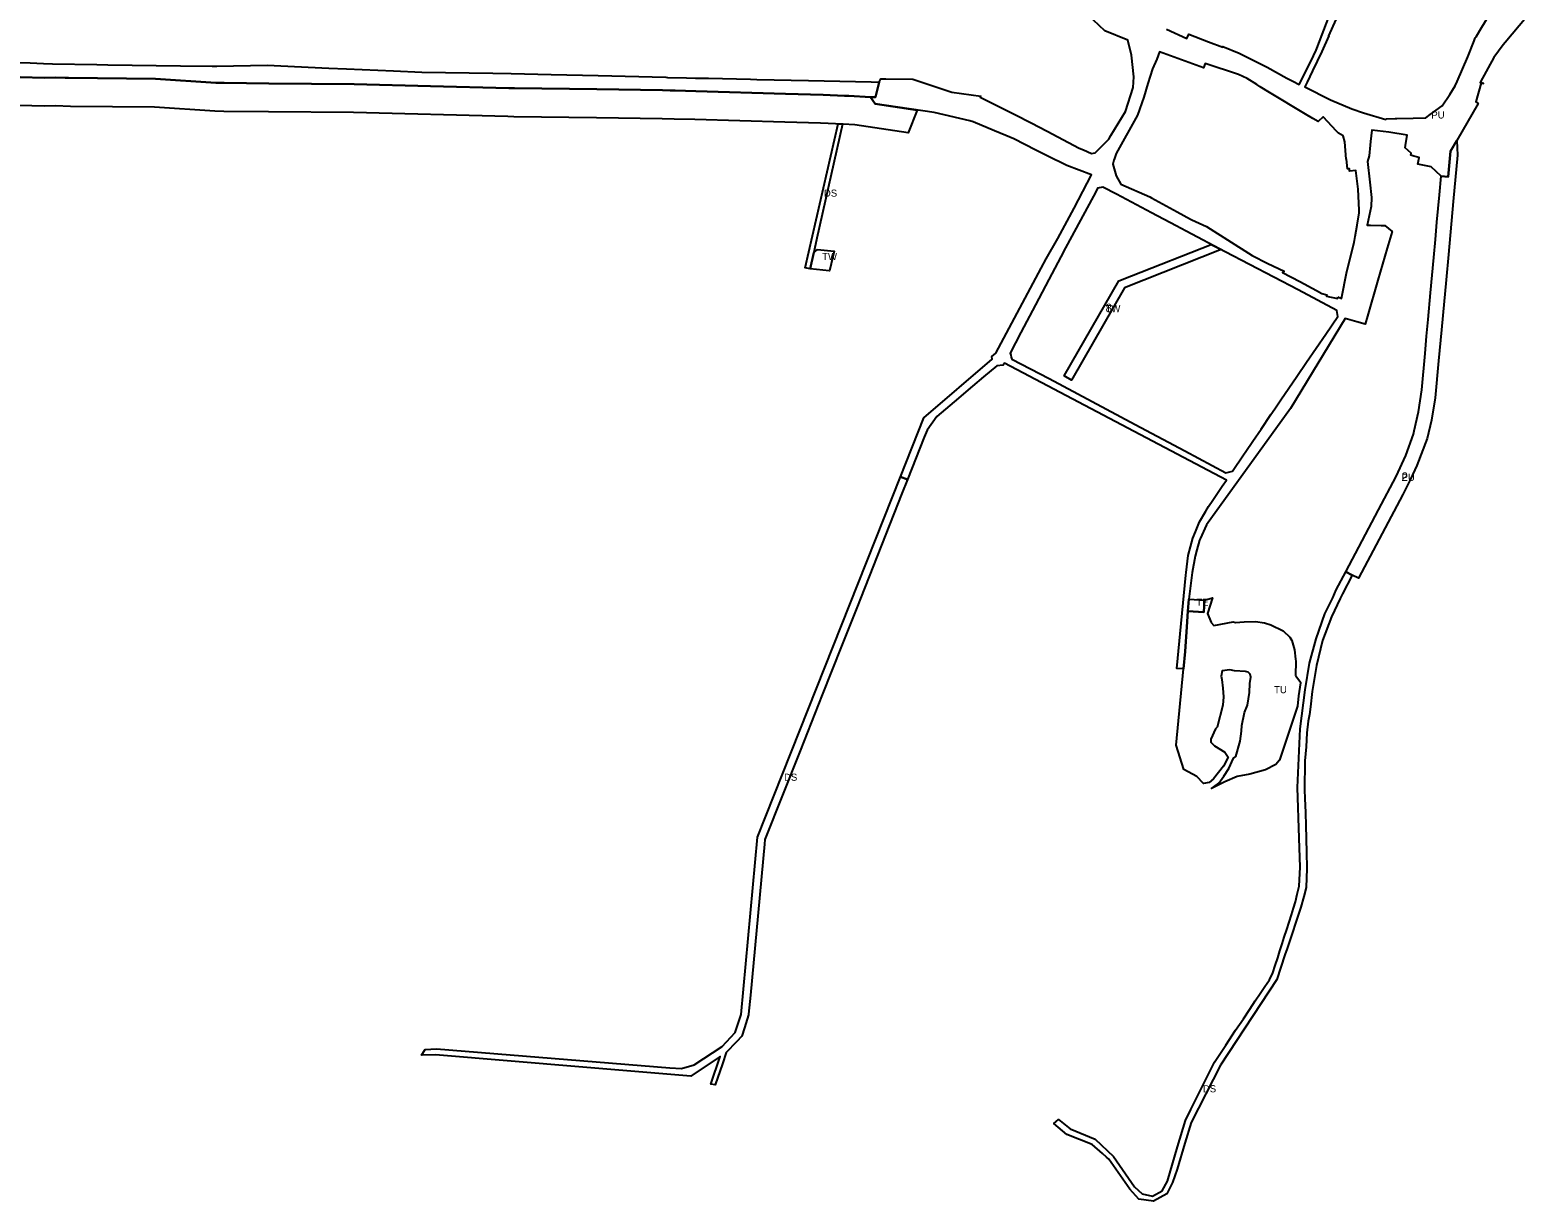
# Model space of a CAD drawing. Extents: x -540396 to -537847, y -1162344 to -1159959.
# Drawn here: x -539100 to -538050, y -1162093 to -1161270 of the extents above; entities that cross this region are included whole.
import ezdxf

# ---------------------------------------------------------------- set-up
doc = ezdxf.new("R2010")
doc.units = 0
for name, color, linetype in [('90320013', 7, 'Continuous'), ('90380013', 7, 'Continuous'), ('90390013', 7, 'Continuous'), ('90390023', 7, 'Continuous'), ('90400013', 7, 'Continuous'), ('90450013', 7, 'Continuous'), ('90450023', 7, 'Continuous'), ('ID_navrh', 7, 'Continuous')]:
    doc.layers.add(name, color=color, linetype=linetype)

msp = doc.modelspace()

# ---------------------------------------------------------------- linework, layer by layer
at = {"layer": '90320013'}
msp.add_lwpolyline([(-539108, -1161292.84), (-539099.9, -1161293.1), (-539090.47, -1161293.43), (-539084.18, -1161293.8), (-539053.1, -1161294.23), (-539045.37, -1161294.34), (-538994.31, -1161295.03), (-538972.25, -1161295.43), (-538971.53, -1161295.41), (-538968.85, -1161295.34), (-538933.47, -1161294.66), (-538890.19, -1161296.72), (-538877.93, -1161297.24), (-538844.86, -1161298.63), (-538824.88, -1161299.47), (-538775.002, -1161300.218), (-538762.23, -1161300.41), (-538734.05, -1161301.26), (-538701.15, -1161301.97), (-538653.67, -1161303.19), (-538652.47, -1161303.22), (-538639.09, -1161303.52), (-538632.77, -1161303.67), (-538623.58, -1161303.88), (-538604.03, -1161304.32), (-538594.08, -1161304.54), (-538589.83, -1161304.64), (-538553.54, -1161305.46), (-538509.52, -1161306.46), (-538503.96, -1161306.59), (-538506.44, -1161317.11), (-538509.92, -1161317.02), (-538525.05, -1161316.29), (-538528.1, -1161316.15), (-538543.18, -1161315.42), (-538569.52, -1161314.68), (-538632.62, -1161312.91), (-538647.15, -1161312.5), (-538650.6, -1161312.4), (-538655.87, -1161312.32), (-538701.99, -1161311.54), (-538759.94, -1161310.85), (-538763.94, -1161310.7), (-538818.82, -1161309.45), (-538872.55, -1161307.97), (-538932.3, -1161307.52), (-538963.6, -1161307.09), (-538965.62, -1161307.06), (-538969.5, -1161306.98), (-539011.91, -1161304.22), (-539072.96, -1161303.55), (-539075.23, -1161303.45), (-539082.25, -1161303.24), (-539089.91, -1161303.49), (-539106.85, -1161302.97)], dxfattribs=at)
for points in [[(-538552.25, -1161437.72), (-538555.781, -1161436.91), (-538532.64, -1161335.957), (-538529.51, -1161336.106), (-538547.55, -1161416.25), (-538549.28, -1161423.93), (-538549.79, -1161426.28)], [(-538815.36, -1161989.8), (-538825.25, -1161990.14), (-538822.66, -1161986.2), (-538814.6, -1161985.57), (-538650.79, -1161999.07), (-538642.69, -1161999.35), (-538633.82, -1161996.81), (-538614, -1161984.1), (-538605, -1161974.15), (-538600.78, -1161961.59), (-538589.29, -1161836.98), (-538488.863, -1161583.734), (-538488.863, -1161583.734), (-538483.93, -1161585.69), (-538487.85, -1161595.59), (-538519.6, -1161675.81), (-538527.46, -1161695.68), (-538530.23, -1161702.68), (-538543.83, -1161737.06), (-538559.39, -1161776.37), (-538584.01, -1161838.63), (-538584.32, -1161841.97), (-538590.02, -1161902.5), (-538594.3, -1161947.9), (-538595.55, -1161961.24), (-538595.61, -1161961.84), (-538598.51, -1161970.95), (-538600.35, -1161976.7), (-538604.09, -1161980.62), (-538611.26, -1161988.13), (-538613.96, -1161996.08), (-538619, -1162010.95), (-538621.98, -1162010.55), (-538615.41, -1161990.91), (-538636.08, -1162004.76), (-538711.96, -1161998.43)], [(-538176.294, -1161650.661), (-538171.84, -1161653.01), (-538171.84, -1161653.01), (-538178.66, -1161665.92), (-538180.3, -1161669.35), (-538186.37, -1161682.08), (-538192.49, -1161698.9), (-538196.85, -1161716.26), (-538199.78, -1161734.53), (-538201.11, -1161745.28), (-538201.84, -1161750.78), (-538202.56, -1161755.54), (-538203.6, -1161763.66), (-538204.12, -1161773.43), (-538205.03, -1161783.21), (-538205.04, -1161789.17), (-538205.3, -1161798.05), (-538205.3, -1161801.86), (-538205.18, -1161803.76), (-538204.93, -1161809.73), (-538204.57, -1161819.51), (-538204.21, -1161829.02), (-538203.97, -1161837.63), (-538203.96, -1161838.54), (-538203.86, -1161847.18), (-538203.5, -1161858.98), (-538204.12, -1161872.38), (-538205.8, -1161878.72), (-538207.73, -1161886.21), (-538217.39, -1161915.26), (-538219.04, -1161919.65), (-538224.69, -1161936.84), (-538264.1, -1161997.03), (-538284.85, -1162037.35), (-538289.23, -1162051.98), (-538294.68, -1162070.18), (-538297.94, -1162079.53), (-538302.01, -1162087.53), (-538311.25, -1162092.59), (-538321.64, -1162091.16), (-538327.97, -1162084.29), (-538342.6, -1162063.19), (-538344.21, -1162061.76), (-538347.08, -1162059.2), (-538354.33, -1162052.73), (-538372.13, -1162045.7), (-538381.26, -1162037.97), (-538377.86, -1162035.24), (-538369.87, -1162041.81), (-538352.19, -1162049.19), (-538339.31, -1162061.37), (-538324.69, -1162082.49), (-538319.3, -1162087.53), (-538312.04, -1162089.17), (-538305.14, -1162085.3), (-538301.51, -1162078.63), (-538294.3, -1162054.42), (-538288.78, -1162035.88), (-538284.97, -1162028.18), (-538268.54, -1161994.93), (-538260.36, -1161983.06), (-538253.62, -1161972.61), (-538248.12, -1161964.52), (-538243.64, -1161957.75), (-538239.81, -1161952.01), (-538236.27, -1161946.69), (-538233.09, -1161941.9), (-538229.92, -1161937.21), (-538227.52, -1161932.23), (-538225.86, -1161927.1), (-538223.99, -1161921.6), (-538222.48, -1161916.89), (-538220.9, -1161911.84), (-538219.43, -1161907.24), (-538217.74, -1161901.9), (-538216.05, -1161896.56), (-538214.44, -1161891.45), (-538213.07, -1161886.83), (-538211.64, -1161882.32), (-538210.46, -1161876.94), (-538208.88, -1161871.32), (-538208.38, -1161857.93), (-538209, -1161837.65), (-538210.23, -1161802.12), (-538209.13, -1161781.4), (-538208.38, -1161760.87), (-538204.78, -1161733.41), (-538201.67, -1161714.79), (-538197.05, -1161697.53), (-538190.95, -1161680.06), (-538185.41, -1161668.8), (-538182.91, -1161663.21)]]:
    msp.add_lwpolyline(points, close=True, dxfattribs=at)
at = {"layer": '90380013'}
msp.add_lwpolyline([(-538270.86, -1161686.12), (-538268.88, -1161688.31), (-538255.36, -1161685.69), (-538253.8, -1161686.12), (-538247.59, -1161685.69), (-538239.76, -1161685.46), (-538233.35, -1161686.41), (-538228.77, -1161687.79), (-538220.27, -1161691.93), (-538215.47, -1161696.4), (-538214.18, -1161698.78), (-538212.27, -1161705.46), (-538211.55, -1161711.92), (-538211.39, -1161713.38), (-538211.49, -1161723.33), (-538211.22, -1161723.71), (-538208.02, -1161728.1), (-538208.14, -1161728.64), (-538209.4, -1161737.76), (-538210.16, -1161744.89), (-538222.78, -1161782.94), (-538225.4, -1161785.83), (-538232.71, -1161789.76), (-538243.63, -1161792.64), (-538252.45, -1161794.29), (-538261.12, -1161797.97), (-538270.48, -1161802.78), (-538265.4, -1161798.93), (-538261.97, -1161794.15), (-538258.35, -1161788.8), (-538255.16, -1161781.52), (-538253.43, -1161780.27), (-538250.47, -1161769.56), (-538249.48, -1161762.51), (-538249.25, -1161758.49), (-538247.3, -1161749.42), (-538245.33, -1161744.12), (-538243.88, -1161735.22), (-538243.7, -1161728.99), (-538243, -1161724.65), (-538243.43, -1161722.42), (-538244.86, -1161721.08), (-538246.7, -1161720.57), (-538254.34, -1161720.22), (-538257.76, -1161719.32), (-538262.99, -1161719.99), (-538263.68, -1161723.89), (-538263.18, -1161726.3), (-538262.59, -1161732.24), (-538262, -1161738.48), (-538262.47, -1161744.28), (-538266.54, -1161759.66), (-538267.72, -1161760.88), (-538271.08, -1161768.03), (-538271.09, -1161770.32), (-538268.45, -1161772.76), (-538261.12, -1161777.24), (-538258.79, -1161780.69), (-538262.18, -1161787.08), (-538269.1, -1161796.05), (-538272.29, -1161798.57), (-538276.25, -1161799.16), (-538280.77, -1161794.28), (-538283.81, -1161792.69), (-538290.07, -1161789.43), (-538295.34, -1161772.3), (-538289.13, -1161706.46), (-538287.82, -1161689.19), (-538287.06, -1161678.11), (-538275.87, -1161678.87), (-538275.39, -1161670.47), (-538269.939, -1161668.865), (-538273.23, -1161679.79)], close=True, dxfattribs=at)
at = {"layer": '90390013'}
msp.add_lwpolyline([(-538547.06, -1161424.15), (-538535.47, -1161425.3), (-538538.69, -1161439.16), (-538539.06, -1161439.12), (-538552.25, -1161437.72), (-538549.79, -1161426.28)], close=True, dxfattribs=at)
at = {"layer": '90390023'}
msp.add_lwpolyline([(-539106.85, -1161302.97), (-539089.91, -1161303.49), (-539082.25, -1161303.24), (-539075.23, -1161303.45), (-539072.96, -1161303.55), (-539011.91, -1161304.22), (-538969.5, -1161306.98), (-538965.62, -1161307.06), (-538963.6, -1161307.09), (-538932.3, -1161307.52), (-538872.55, -1161307.97), (-538818.82, -1161309.45), (-538763.94, -1161310.7), (-538759.94, -1161310.85), (-538701.99, -1161311.54), (-538655.87, -1161312.32), (-538650.6, -1161312.4), (-538647.15, -1161312.5), (-538632.62, -1161312.91), (-538569.52, -1161314.68), (-538543.18, -1161315.42), (-538528.1, -1161316.15), (-538525.05, -1161316.29), (-538509.92, -1161317.02), (-538506.76, -1161321.76), (-538477.098, -1161326.205), (-538483.483, -1161342.179), (-538520.963, -1161336.51), (-538529.042, -1161336.128), (-538545.041, -1161335.37), (-538570.081, -1161334.672), (-538633.182, -1161332.902), (-538647.722, -1161332.492), (-538656.191, -1161332.317), (-538702.278, -1161331.538), (-538760.434, -1161330.846), (-538764.566, -1161330.69), (-538872.877, -1161327.968), (-538932.513, -1161327.519), (-538963.886, -1161327.088), (-538970.356, -1161326.967), (-539012.669, -1161324.213), (-539071.627, -1161323.569), (-539082.223, -1161323.25), (-539089.891, -1161323.5), (-539107.636, -1161322.955)], dxfattribs=at)
msp.add_lwpolyline([(-538270.781, -1161420.551), (-538263.785, -1161424.239), (-538331.537, -1161450.995), (-538368.841, -1161515.876), (-538374.043, -1161512.886), (-538335.693, -1161446.185), (-538335.693, -1161446.185), (-538326.739, -1161442.649)], close=True, dxfattribs=at)
at = {"layer": '90400013'}
msp.add_lwpolyline([(-538275.39, -1161670.47), (-538275.87, -1161678.87), (-538287.06, -1161678.11), (-538286.52, -1161669.82)], close=True, dxfattribs=at)
at = {"layer": '90450013'}
for points in [[(-538049.68, -1161261.08), (-538064.4, -1161278.84), (-538065.66, -1161280.36), (-538072.34, -1161289.23), (-538081.57, -1161306.27), (-538081.87, -1161306.89), (-538079.54, -1161307.64), (-538081.21, -1161307.11), (-538084.91, -1161320.36), (-538083.28, -1161321.48), (-538098.33, -1161347.51), (-538102.7, -1161355.1), (-538104.328, -1161373.143), (-538109.35, -1161372.69), (-538109.35, -1161372.69), (-538116.27, -1161366.02), (-538125.65, -1161364.3), (-538124.76, -1161359.53), (-538128.42, -1161358.51), (-538130.7, -1161357.87), (-538130.46, -1161356.58), (-538134.63, -1161352.62), (-538134.27, -1161351.19), (-538133.05, -1161343.78), (-538145.94, -1161341.63), (-538157.99, -1161340.22), (-538158.88, -1161348.18), (-538159.17, -1161350.84), (-538159.86, -1161358.36), (-538161.01, -1161362.34), (-538159.49, -1161376.86), (-538158.24, -1161387.68), (-538158.44, -1161393.935), (-538159.25, -1161397.29), (-538161.279, -1161406.927), (-538158.84, -1161406.99), (-538151.43, -1161407.18), (-538148.816, -1161407.247), (-538148.816, -1161407.247), (-538143.76, -1161411.41), (-538147.15, -1161423.13), (-538153.85, -1161445.79), (-538160.97, -1161470.87), (-538162.64, -1161476.63), (-538168.499, -1161474.957), (-538168.499, -1161474.957), (-538176.803, -1161472.585), (-538215.114, -1161535.799), (-538274.09, -1161617.5), (-538278.46, -1161627.42), (-538278.85, -1161628.3), (-538280.77, -1161635.09), (-538282.05, -1161639.61), (-538284.16, -1161651.03), (-538286.52, -1161669.82), (-538287.06, -1161678.11), (-538287.82, -1161689.19), (-538289.13, -1161706.46), (-538290.276, -1161718.619), (-538294.95, -1161718.38), (-538291.91, -1161686.93), (-538288.62, -1161652.89), (-538288.43, -1161650.95), (-538286.8, -1161639.06), (-538283.65, -1161626.88), (-538281.82, -1161622.49), (-538278.9, -1161615.48), (-538274.56, -1161608.01), (-538272.67, -1161604.76), (-538269.63, -1161600.25), (-538262.93, -1161590.34), (-538260.04, -1161586.07), (-538415.779, -1161503.987), (-538415.779, -1161503.987), (-538416.71, -1161505.29), (-538421.3, -1161505.81), (-538430.5, -1161513.59), (-538438.26, -1161520.16), (-538451.19, -1161531.09), (-538463.41, -1161541.42), (-538470.18, -1161550.96), (-538472.2, -1161556.08), (-538483.93, -1161585.69), (-538488.863, -1161583.734), (-538472.42, -1161542.27), (-538424.57, -1161501.23), (-538424.71, -1161499.28), (-538424.71, -1161499.28), (-538421.84, -1161496.84), (-538390.06, -1161437.17), (-538386.65, -1161430.77), (-538378.36, -1161416.32), (-538367.06, -1161395), (-538354.74, -1161371.76), (-538372.09, -1161365.13), (-538385.88, -1161358.32), (-538393.83, -1161354.4), (-538409.42, -1161346.44), (-538414.94, -1161344.09), (-538422.83, -1161340.73), (-538437.81, -1161334.36), (-538440.24, -1161333.79), (-538465.32, -1161327.97), (-538506.76, -1161321.76), (-538509.92, -1161317.02), (-538506.44, -1161317.11), (-538503.96, -1161306.59), (-538502.73, -1161304.19), (-538499.22, -1161304.24), (-538480.31, -1161304.47), (-538461.33, -1161310.84), (-538452.8, -1161313.7), (-538432.46, -1161316.41), (-538432.99, -1161317.2), (-538420.8, -1161323.23), (-538408.61, -1161329.26), (-538397.16, -1161335.13), (-538385.82, -1161341.07), (-538363.4, -1161353), (-538360.35, -1161354.12), (-538354.83, -1161356.59), (-538352.17, -1161356.14), (-538342.71, -1161346.6), (-538341.14, -1161344.01), (-538330.98, -1161327.25), (-538325.53, -1161310.24), (-538325.1, -1161302.89), (-538326.63, -1161287.66), (-538329.39, -1161277.17), (-538345.34, -1161270.42), (-538357.37, -1161259.2)], [(-538302.11, -1161269.38), (-538287.76, -1161276), (-538286.52, -1161272.83), (-538272.53, -1161278.26), (-538262.65, -1161282.09), (-538262.47, -1161281.62), (-538251.16, -1161286.21), (-538231.47, -1161296.16), (-538217.56, -1161303.7), (-538213.35, -1161305.89), (-538209.04, -1161308.12), (-538200.82, -1161292.15), (-538197.13, -1161284.14), (-538196.6, -1161282.98), (-538187.83, -1161260.14)], [(-538183.26, -1161262.48), (-538188.28, -1161273.97), (-538188.09, -1161274.06), (-538192.99, -1161284.98), (-538199.55, -1161298.56), (-538203.3, -1161306.56), (-538204.96, -1161309.98), (-538186.92, -1161319.02), (-538171.94, -1161325.41), (-538163.93, -1161328.23), (-538148.03, -1161332.81), (-538147.7, -1161332.31), (-538141.49, -1161332.07), (-538140.41, -1161332.05), (-538129.01, -1161331.79), (-538120.06, -1161331.71), (-538117.04, -1161329.42), (-538108.69, -1161323.1), (-538103.16, -1161315.27), (-538099.45, -1161309.07), (-538098.16, -1161306.15), (-538090.55, -1161288.74), (-538086.13, -1161277.58), (-538085.32, -1161275.54), (-538084.82, -1161274.71), (-538082.21, -1161270.41), (-538077.49, -1161262.62)]]:
    msp.add_lwpolyline(points, dxfattribs=at)
for points in [[(-538181.8, -1161457.36), (-538179.22, -1161458.53), (-538175.42, -1161439.51), (-538170.38, -1161419.16), (-538170.28, -1161418.74), (-538170.15, -1161417.8), (-538169.63, -1161414.89), (-538168.36, -1161406.96), (-538166.88, -1161398.42), (-538166.78, -1161396.39), (-538167.65, -1161381.74), (-538169.2, -1161368.61), (-538173.55, -1161369.12), (-538173.72, -1161367.39), (-538175.02, -1161367.51), (-538175.74, -1161360.78), (-538176.07, -1161360.74), (-538176.97, -1161348.56), (-538178.18, -1161344.37), (-538181.48, -1161342.49), (-538182.83, -1161341.02), (-538192.16, -1161330.85), (-538195.72, -1161334.2), (-538199.37, -1161332.11), (-538204.65, -1161329.08), (-538229.72, -1161313.75), (-538236.28, -1161309.78), (-538238.78, -1161308.21), (-538245.54, -1161304.08), (-538251.65, -1161301.22), (-538274.94, -1161293.48), (-538276.06, -1161296.55), (-538307.06, -1161285.3), (-538308.93, -1161290.39), (-538312.04, -1161297.25), (-538315.13, -1161307.48), (-538318.03, -1161317.06), (-538322.43, -1161329.72), (-538337.56, -1161356.74), (-538338.74, -1161360.11), (-538339.1, -1161361.33), (-538339.92, -1161364.11), (-538337.46, -1161372.44), (-538334.24, -1161378.25), (-538313.81, -1161387.14), (-538312.7, -1161387.75), (-538294.53, -1161397.71), (-538285.31, -1161402.76), (-538284.29, -1161403.23), (-538274.16, -1161407.99), (-538241.99, -1161428.28), (-538230.93, -1161434), (-538219.6, -1161439.26), (-538220.61, -1161440.22), (-538208.43, -1161446.71), (-538196.8, -1161453.04), (-538193.11, -1161455.1), (-538189.54, -1161455.87), (-538189.76, -1161456.98), (-538182.05, -1161458.56)], [(-538260.57, -1161580.99), (-538255.87, -1161579.9), (-538248.12, -1161568.43), (-538246.44, -1161565.95), (-538241.5, -1161558.7), (-538235.77, -1161550.32), (-538228.81, -1161540.12), (-538225.99, -1161535.98), (-538221.77, -1161529.82), (-538210.53, -1161513.31), (-538203.78, -1161503.39), (-538197, -1161493.44), (-538190.27, -1161483.55), (-538181.83, -1161471.15), (-538182.49, -1161467.05), (-538209.78, -1161452.55), (-538260.9, -1161425.76), (-538288.27, -1161411.33), (-538295.31, -1161407.59), (-538312.63, -1161398.38), (-538337.25, -1161385.34), (-538346.88, -1161380.33), (-538350.63, -1161381.08), (-538351.85, -1161383.59), (-538362.54, -1161403.54), (-538372.93, -1161422.91), (-538376.32, -1161429.29), (-538384.85, -1161445.29), (-538394.1, -1161462.9), (-538404.31, -1161482.44), (-538411.96, -1161496.96), (-538411.49, -1161498.45), (-538411.12, -1161499.65), (-538410.69, -1161501.11), (-538384.43, -1161514.85), (-538324.1, -1161546.99), (-538289.21, -1161565.47)]]:
    msp.add_lwpolyline(points, close=True, dxfattribs=at)
at = {"layer": '90450023'}
msp.add_lwpolyline([(-538098.33, -1161347.51), (-538097.93, -1161357.873), (-538100.87, -1161390.459), (-538104.21, -1161427.559), (-538105.83, -1161445.499), (-538108.071, -1161470.4), (-538109.042, -1161480.662), (-538111.106, -1161502.38), (-538113.558, -1161528.383), (-538116.155, -1161544.067), (-538119.198, -1161556.881), (-538126.35, -1161575.961), (-538130.738, -1161585.539), (-538136.252, -1161596.344), (-538167.28, -1161655.083), (-538171.84, -1161653.01), (-538176.294, -1161650.661), (-538153.25, -1161606.95), (-538140.92, -1161583.57), (-538134.08, -1161568.88), (-538128.73, -1161553.82), (-538128.19, -1161551.49), (-538125.13, -1161538.2), (-538122.76, -1161522.74), (-538120.47, -1161497.15), (-538119.48, -1161485.1), (-538118.46, -1161473.2), (-538116.79, -1161454.61), (-538114.54, -1161429.74), (-538113.33, -1161417.17), (-538112.24, -1161405.01), (-538110.51, -1161385.64), (-538109.35, -1161372.69), (-538104.328, -1161373.143), (-538102.7, -1161355.1)], close=True, dxfattribs=at)

# ---------------------------------------------------------------- texts
at = {"layer": '90320013'}
for rotation, p in [(360, (-538542.646, -1161387.034)), (0, (-538570.627, -1161797.342)), (0, (-538276.55, -1162016.181))]:
    msp.add_text('DS', height=5, rotation=rotation, dxfattribs=at).set_placement(p)
at = {"layer": '90380013'}
msp.add_text('TU', height=5, rotation=360, dxfattribs=at).set_placement((-538226.555, -1161735.823))
at = {"layer": '90390013'}
msp.add_text('TW', height=5, rotation=0, dxfattribs=at).set_placement((-538543.86, -1161431.539))
at = {"layer": '90390023'}
msp.add_text('TW', height=5, rotation=360, dxfattribs=at).set_placement((-538344.898, -1161468.213))
at = {"layer": '90400013'}
msp.add_text('TE', height=5, rotation=0, dxfattribs=at).set_placement((-538281.213, -1161674.345))
at = {"layer": '90450013'}
msp.add_text('PU', height=5, rotation=360, dxfattribs=at).set_placement((-538116.167, -1161332.124))
at = {"layer": '90450023'}
msp.add_text('PU', height=5, rotation=0, dxfattribs=at).set_placement((-538137.112, -1161586.682))
at = {"layer": 'ID_navrh'}
for s, rotation, p in [('8', 360, (-538344.898, -1161468.213)), ('2', 0, (-538137.112, -1161586.682))]:
    msp.add_text(s, height=6, rotation=rotation, dxfattribs=at).set_placement(p)

doc.saveas('drawing.dxf')
